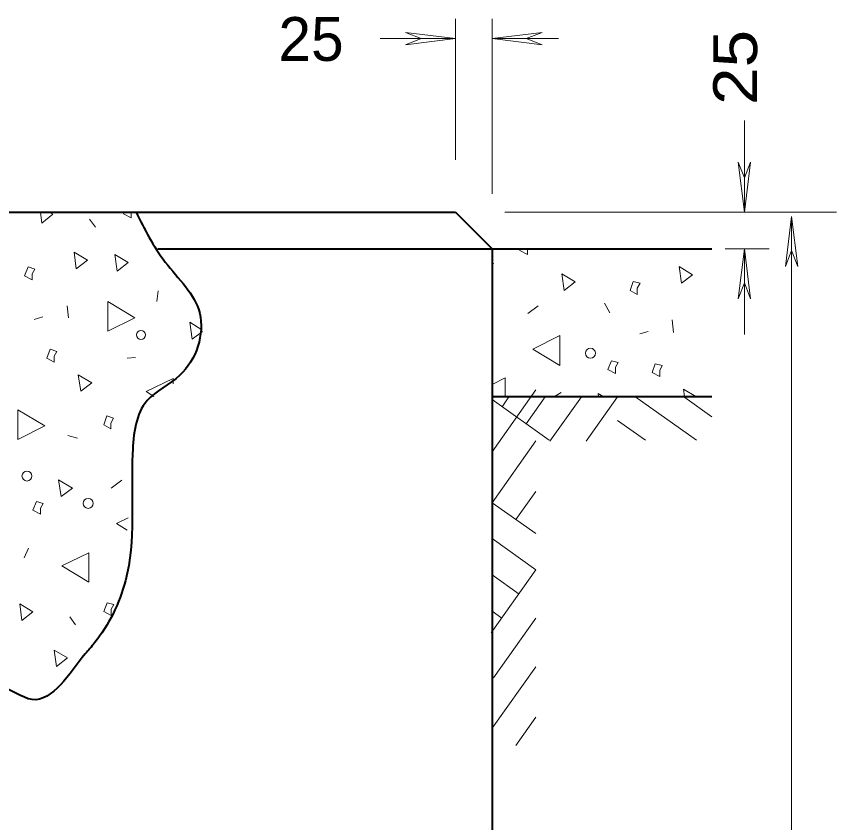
# Model space of a CAD drawing. Extents: x 312583 to 312854, y 144419 to 144597.
# Drawn here: x 312645.99 to 312660.21, y 144456.42 to 144470.39 of the extents above; entities that cross this region are included whole.
import ezdxf

# ---------------------------------------------------------------- set-up
doc = ezdxf.new("R2010")
doc.units = 0
doc.header["$LTSCALE"] = 0.3
doc.layers.add('1', color=7, linetype='Continuous', lineweight=25)
doc.layers.add('2', color=7, linetype='Continuous', lineweight=13)

msp = doc.modelspace()

# ---------------------------------------------------------------- linework, layer by layer
at = {"layer": '1', "lineweight": 40}
for p, q in [((312628.04, 144467.0035), (312653.6006, 144467.0035)), ((312653.6006, 144467.0035), (312654.237, 144466.3672)), ((312648.441, 144466.3672), (312658.0473, 144466.3672)), ((312654.237, 144466.3672), (312654.237, 144444.0035)), ((312654.237, 144463.8065), (312658.0473, 144463.8065))]:
    msp.add_line(p, q, dxfattribs=at)
msp.add_spline([(312648.0653, 144467.0035), (312648.5713, 144466.1372), (312649.1693, 144465.2479), (312648.8243, 144464.1745), (312648.257, 144463.7375), (312648.004, 144462.8175), (312647.8813, 144460.6095), (312647.3446, 144459.5362), (312647.1836, 144459.3445), (312646.2636, 144458.5549), (312645.7116, 144458.7849), (312644.8453, 144458.6775), (312644.0786, 144458.7465), (312643.22, 144458.5319), (312642.162, 144458.4935), (312641.5333, 144458.7005), (312640.805, 144458.3939), (312640.713, 144458.3019), (312640.0076, 144458.4092), (312638.9113, 144457.7345), (312638.6276, 144457.6732), (312637.562, 144458.2329), (312635.9673, 144458.3095), (312635.6223, 144457.8495)], degree=3, dxfattribs=at)
at = {"layer": '2'}
for p, q in [((312653.6006, 144467.9082), (312653.6006, 144470.3539)), ((312654.237, 144467.3179), (312654.237, 144470.3539)), ((312652.7343, 144470.1162), (312653.0103, 144470.0089)), ((312653.6006, 144470.0089), (312652.7343, 144470.1162)), ((312654.237, 144470.0089), (312655.1033, 144470.1162)), ((312655.1033, 144470.1162), (312654.8273, 144470.0089)), ((312652.2973, 144470.0089), (312653.6006, 144470.0089)), ((312652.7343, 144469.9015), (312653.0103, 144470.0089)), ((312653.6006, 144470.0089), (312652.7343, 144469.9015)), ((312654.237, 144470.0089), (312655.387, 144470.0089)), ((312654.237, 144470.0089), (312655.1033, 144469.9015)), ((312655.1033, 144469.9015), (312654.8273, 144470.0089)), ((312658.611, 144467.0035), (312658.611, 144468.5905)), ((312658.5037, 144467.8699), (312658.611, 144467.5939)), ((312658.611, 144467.0035), (312658.5037, 144467.8699)), ((312658.7183, 144467.8699), (312658.611, 144467.5939)), ((312658.611, 144467.0035), (312658.7183, 144467.8699)), ((312646.4093, 144467.0035), (312646.4323, 144466.8119)), ((312654.4593, 144467.0035), (312660.2096, 144467.0035)), ((312659.4297, 144466.9287), (312659.3223, 144466.0624)), ((312659.4297, 144443.9287), (312659.4297, 144466.9287)), ((312659.4297, 144466.9287), (312659.537, 144466.0624)), ((312647.2603, 144466.8809), (312647.36, 144466.7429)), ((312658.2764, 144466.3672), (312659.0403, 144466.3672)), ((312658.611, 144466.3672), (312658.5037, 144465.5009)), ((312658.611, 144464.8799), (312658.611, 144466.3672)), ((312658.611, 144466.3672), (312658.7183, 144465.5009)), ((312659.3223, 144466.0624), (312659.4297, 144466.3384)), ((312659.537, 144466.0624), (312659.4297, 144466.3384)), ((312654.237, 144466.1219), (312654.2676, 144466.1142)), ((312658.5037, 144465.5009), (312658.611, 144465.7769)), ((312658.7183, 144465.5009), (312658.611, 144465.7769)), ((312648.4256, 144465.4549), (312648.4486, 144465.6389)), ((312646.8693, 144465.3782), (312646.8923, 144465.1712)), ((312655.0343, 144465.3782), (312654.858, 144465.2479)), ((312656.1843, 144465.4242), (312656.2763, 144465.2555)), ((312646.302, 144465.1405), (312646.4476, 144465.1865)), ((312657.3573, 144465.1329), (312657.3803, 144464.9182)), ((312649.039, 144464.8032), (312649.2153, 144464.9335)), ((312656.7976, 144464.8952), (312656.9433, 144464.9335)), ((312647.912, 144464.4735), (312648.0576, 144464.4812)), ((312654.996, 144463.9215), (312654.237, 144462.8482)), ((312654.5283, 144463.7989), (312654.4133, 144463.6302)), ((312655.157, 144463.7989), (312654.8273, 144463.3312)), ((312655.7856, 144463.7989), (312655.2413, 144463.0322)), ((312655.318, 144463.8065), (312655.433, 144463.8755)), ((312656.4143, 144463.7989), (312655.87, 144463.0322)), ((312657.779, 144463.0475), (312656.7133, 144463.8065)), ((312655.226, 144463.0475), (312654.237, 144463.7529)), ((312658.0473, 144463.4539), (312657.5796, 144463.7912)), ((312656.8973, 144463.0475), (312656.4143, 144463.3925)), ((312646.8846, 144463.1319), (312647.0533, 144463.0859)), ((312654.996, 144463.0399), (312654.237, 144461.9665)), ((312647.82, 144462.3575), (312647.636, 144462.2195)), ((312654.996, 144462.1582), (312654.651, 144461.6752)), ((312654.237, 144461.9665), (312654.996, 144461.4299)), ((312654.237, 144461.3455), (312654.996, 144460.8012)), ((312646.2023, 144461.1769), (312646.1256, 144461.0082)), ((312654.996, 144460.8012), (312654.2216, 144459.7125)), ((312654.237, 144460.7169), (312654.7046, 144460.3795)), ((312646.9153, 144459.9885), (312647.015, 144459.8505)), ((312654.237, 144460.0882), (312654.4056, 144459.9655)), ((312654.996, 144459.9655), (312654.26, 144458.9305)), ((312654.996, 144459.1222), (312654.237, 144458.0565)), ((312654.996, 144458.2482), (312654.651, 144457.7575))]:
    msp.add_line(p, q, dxfattribs=at)
for points in [[(312646.4323, 144466.8119), (312646.624, 144466.9652), (312646.555, 144467.0035)], [(312647.866, 144467.0035), (312647.8506, 144466.9729), (312647.981, 144466.9039), (312647.981, 144467.0035)], [(312648.2263, 144466.7275), (312648.2186, 144466.7199), (312648.234, 144466.7122)], [(312654.7276, 144466.3672), (312654.72, 144466.3365), (312654.8503, 144466.2675), (312654.8503, 144466.3672)], [(312649.2076, 144464.9642), (312649.0006, 144465.0945), (312649.039, 144464.8032)], [(312648.7093, 144464.0289), (312648.7093, 144464.1209), (312648.2416, 144463.8909), (312648.372, 144463.8065)], [(312654.467, 144463.8065), (312654.467, 144464.1285), (312654.237, 144464.0135)], [(312656.1613, 144463.8065), (312656.077, 144463.8602), (312656.0846, 144463.8065)], [(312657.7713, 144463.8065), (312657.5566, 144463.9369), (312657.572, 144463.8065)], [(312647.9273, 144461.7059), (312647.728, 144461.6062), (312647.912, 144461.4912)]]:
    msp.add_lwpolyline(points, dxfattribs=at)
for points in [[(312647.0303, 144466.0222), (312647.222, 144466.1679), (312646.992, 144466.3059)], [(312647.7356, 144465.9762), (312647.9273, 144466.1295), (312647.6973, 144466.2675)], [(312646.2636, 144465.9302), (312646.3096, 144466.0145), (312646.1946, 144466.0529), (312646.1333, 144465.8995), (312646.2636, 144465.8305)], [(312655.4866, 144465.6465), (312655.6783, 144465.7922), (312655.4483, 144465.9302)], [(312657.5183, 144465.7692), (312657.71, 144465.9149), (312657.48, 144466.0605)], [(312656.7516, 144465.6849), (312656.8053, 144465.7692), (312656.6826, 144465.7999), (312656.629, 144465.6465), (312656.7516, 144465.5775)], [(312647.5746, 144465.4549), (312647.5746, 144464.9412), (312648.0423, 144465.1712)], [(312655.41, 144464.3432), (312655.41, 144464.8645), (312654.9423, 144464.6269)], [(312646.647, 144464.5042), (312646.693, 144464.5885), (312646.578, 144464.6269), (312646.5166, 144464.4735), (312646.647, 144464.4045)], [(312656.376, 144464.3125), (312656.422, 144464.3969), (312656.307, 144464.4275), (312656.2456, 144464.2742), (312656.376, 144464.2052)], [(312657.1426, 144464.2589), (312657.1886, 144464.3432), (312657.066, 144464.3739), (312657.0123, 144464.2205), (312657.1426, 144464.1515)], [(312647.107, 144463.8985), (312647.2986, 144464.0442), (312647.061, 144464.1822)], [(312646.0183, 144463.5765), (312646.0183, 144463.0629), (312646.486, 144463.3005)], [(312647.6283, 144463.3465), (312647.6743, 144463.4309), (312647.5593, 144463.4692), (312647.5056, 144463.3159), (312647.6283, 144463.2469)], [(312646.7696, 144462.0739), (312646.9613, 144462.2195), (312646.7236, 144462.3652)], [(312646.4093, 144461.8745), (312646.4553, 144461.9512), (312646.3403, 144461.9895), (312646.279, 144461.8362), (312646.4093, 144461.7672)], [(312647.245, 144460.5865), (312647.245, 144461.1002), (312646.7773, 144460.8702)], [(312646.0873, 144459.9272), (312646.279, 144460.0729), (312646.049, 144460.2109)], [(312647.636, 144460.1189), (312647.682, 144460.2032), (312647.567, 144460.2339), (312647.5056, 144460.0805), (312647.636, 144460.0115)], [(312646.6853, 144459.1299), (312646.877, 144459.2755), (312646.647, 144459.4135)]]:
    msp.add_lwpolyline(points, close=True, dxfattribs=at)
for centre, radius in [((312648.1507, 144464.8747), 0.0784), ((312655.942, 144464.5563), 0.0865), ((312646.1744, 144462.4288), 0.0865), ((312647.2356, 144461.9548), 0.0865)]:
    msp.add_circle(centre, radius, dxfattribs=at)

# ---------------------------------------------------------------- texts
msp.add_text('25', height=0.76, dxfattribs=at).set_placement((312650.5341, 144469.6227))
at = {"layer": '2', "width": 1.15}
msp.add_text('25 ', height=0.76, rotation=90, dxfattribs=at).set_placement((312658.8317, 144468.8598))

doc.saveas('drawing.dxf')
